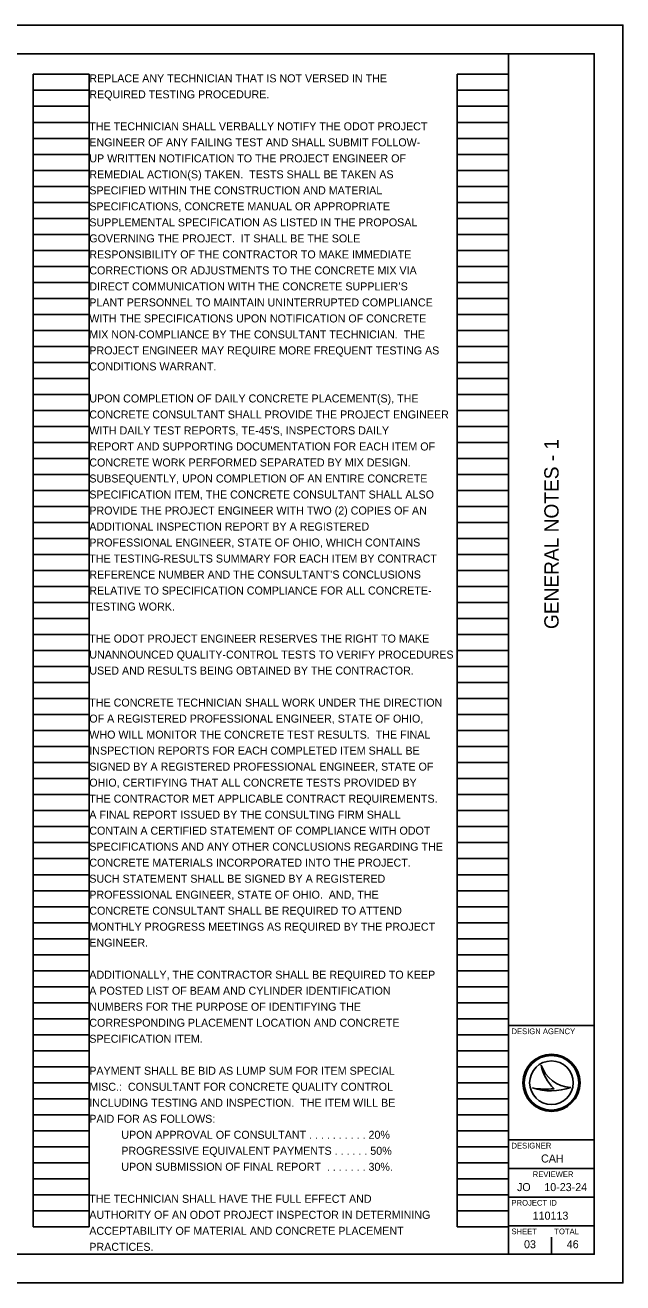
# Model space of a CAD drawing. Extents: x -15.3 to 74.8, y -11.5 to 47.6.
# Drawn here: x 23.54 to 34, y 0 to 22 of the extents above; entities that cross this region are included whole.
import ezdxf

# ---------------------------------------------------------------- set-up
doc = ezdxf.new("R2010")
doc.units = 0
for name, color, linetype in [('Default', 7, 'Continuous'), ('SH_Border', 7, 'Continuous'), ('SH_Cut_Line', 7, 'Continuous'), ('SH_Data', 7, 'Continuous')]:
    doc.layers.add(name, color=color, linetype=linetype)

msp = doc.modelspace()

# ---------------------------------------------------------------- linework, layer by layer
at = {"layer": 'SH_Border'}
for p, q in [((32, 0.5), (32, 21.5)), ((32, 4.5), (33.5, 4.5)), ((32, 2.5), (33.5, 2.5)), ((32, 2), (33.5, 2)), ((32, 1.5), (33.5, 1.5)), ((32, 1), (33.5, 1))]:
    msp.add_line(p, q, dxfattribs=at)
msp.add_lwpolyline([(1.5, 21.5), (33.5, 21.5), (33.5, 0.5), (1.5, 0.5)], close=True, dxfattribs=at)
at = {"layer": 'SH_Cut_Line'}
msp.add_lwpolyline([(0, 0), (34, 0), (34, 22), (0, 22)], close=True, dxfattribs=at)
at = {"layer": 'SH_Data'}
for p, q in [((23.68, 0.98), (23.68, 21.14)), ((23.68, 21.14), (24.66, 21.14)), ((24.66, 0.98), (24.66, 21.14)), ((31.1, 0.98), (31.1, 21.14)), ((31.1, 21.14), (32, 21.14)), ((32, 0.98), (32, 21.14)), ((23.68, 20.86), (24.66, 20.86)), ((31.1, 20.86), (32, 20.86)), ((23.68, 20.58), (24.66, 20.58)), ((31.1, 20.58), (32, 20.58)), ((23.68, 20.3), (24.66, 20.3)), ((31.1, 20.3), (32, 20.3)), ((23.68, 20.02), (24.66, 20.02)), ((31.1, 20.02), (32, 20.02)), ((23.68, 19.74), (24.66, 19.74)), ((31.1, 19.74), (32, 19.74)), ((23.68, 19.46), (24.66, 19.46)), ((31.1, 19.46), (32, 19.46)), ((23.68, 19.18), (24.66, 19.18)), ((31.1, 19.18), (32, 19.18)), ((23.68, 18.9), (24.66, 18.9)), ((31.1, 18.9), (32, 18.9)), ((23.68, 18.62), (24.66, 18.62)), ((31.1, 18.62), (32, 18.62)), ((23.68, 18.34), (24.66, 18.34)), ((31.1, 18.34), (32, 18.34)), ((23.68, 18.06), (24.66, 18.06)), ((31.1, 18.06), (32, 18.06)), ((23.68, 17.78), (24.66, 17.78)), ((31.1, 17.78), (32, 17.78)), ((23.68, 17.5), (24.66, 17.5)), ((31.1, 17.5), (32, 17.5)), ((23.68, 17.22), (24.66, 17.22)), ((31.1, 17.22), (32, 17.22)), ((23.68, 16.94), (24.66, 16.94)), ((31.1, 16.94), (32, 16.94)), ((23.68, 16.66), (24.66, 16.66)), ((31.1, 16.66), (32, 16.66)), ((23.68, 16.38), (24.66, 16.38)), ((31.1, 16.38), (32, 16.38)), ((23.68, 16.1), (24.66, 16.1)), ((31.1, 16.1), (32, 16.1)), ((23.68, 15.82), (24.66, 15.82)), ((31.1, 15.82), (32, 15.82)), ((23.68, 15.54), (24.66, 15.54)), ((31.1, 15.54), (32, 15.54)), ((23.68, 15.26), (24.66, 15.26)), ((31.1, 15.26), (32, 15.26)), ((23.68, 14.98), (24.66, 14.98)), ((31.1, 14.98), (32, 14.98)), ((23.68, 14.7), (24.66, 14.7)), ((31.1, 14.7), (32, 14.7)), ((23.68, 14.42), (24.66, 14.42)), ((31.1, 14.42), (32, 14.42)), ((23.68, 14.14), (24.66, 14.14)), ((31.1, 14.14), (32, 14.14)), ((23.68, 13.86), (24.66, 13.86)), ((31.1, 13.86), (32, 13.86)), ((23.68, 13.58), (24.66, 13.58)), ((31.1, 13.58), (32, 13.58)), ((23.68, 13.3), (24.66, 13.3)), ((31.1, 13.3), (32, 13.3)), ((23.68, 13.02), (24.66, 13.02)), ((31.1, 13.02), (32, 13.02)), ((23.68, 12.74), (24.66, 12.74)), ((31.1, 12.74), (32, 12.74)), ((23.68, 12.46), (24.66, 12.46)), ((31.1, 12.46), (32, 12.46)), ((23.68, 12.18), (24.66, 12.18)), ((31.1, 12.18), (32, 12.18)), ((23.68, 11.9), (24.66, 11.9)), ((31.1, 11.9), (32, 11.9)), ((23.68, 11.62), (24.66, 11.62)), ((31.1, 11.62), (32, 11.62)), ((23.68, 11.34), (24.66, 11.34)), ((31.1, 11.34), (32, 11.34)), ((23.68, 11.06), (24.66, 11.06)), ((31.1, 11.06), (32, 11.06)), ((23.68, 10.78), (24.66, 10.78)), ((31.1, 10.78), (32, 10.78)), ((23.68, 10.5), (24.66, 10.5)), ((31.1, 10.5), (32, 10.5)), ((23.68, 10.22), (24.66, 10.22)), ((31.1, 10.22), (32, 10.22)), ((23.68, 9.94), (24.66, 9.94)), ((31.1, 9.94), (32, 9.94)), ((23.68, 9.66), (24.66, 9.66)), ((31.1, 9.66), (32, 9.66)), ((23.68, 9.38), (24.66, 9.38)), ((31.1, 9.38), (32, 9.38)), ((23.68, 9.1), (24.66, 9.1)), ((31.1, 9.1), (32, 9.1)), ((23.68, 8.82), (24.66, 8.82)), ((31.1, 8.82), (32, 8.82)), ((23.68, 8.54), (24.66, 8.54)), ((31.1, 8.54), (32, 8.54)), ((23.68, 8.26), (24.66, 8.26)), ((31.1, 8.26), (32, 8.26)), ((23.68, 7.98), (24.66, 7.98)), ((31.1, 7.98), (32, 7.98)), ((23.68, 7.7), (24.66, 7.7)), ((31.1, 7.7), (32, 7.7)), ((23.68, 7.42), (24.66, 7.42)), ((31.1, 7.42), (32, 7.42)), ((23.68, 7.14), (24.66, 7.14)), ((31.1, 7.14), (32, 7.14)), ((23.68, 6.86), (24.66, 6.86)), ((31.1, 6.86), (32, 6.86)), ((23.68, 6.58), (24.66, 6.58)), ((31.1, 6.58), (32, 6.58)), ((23.68, 6.3), (24.66, 6.3)), ((31.1, 6.3), (32, 6.3)), ((23.68, 6.02), (24.66, 6.02)), ((31.1, 6.02), (32, 6.02)), ((23.68, 5.74), (24.66, 5.74)), ((31.1, 5.74), (32, 5.74)), ((23.68, 5.46), (24.66, 5.46)), ((31.1, 5.46), (32, 5.46)), ((23.68, 5.18), (24.66, 5.18)), ((31.1, 5.18), (32, 5.18)), ((23.68, 4.9), (24.66, 4.9)), ((31.1, 4.9), (32, 4.9)), ((23.68, 4.62), (24.66, 4.62)), ((31.1, 4.62), (32, 4.62)), ((23.68, 4.34), (24.66, 4.34)), ((31.1, 4.34), (32, 4.34)), ((23.68, 4.06), (24.66, 4.06)), ((31.1, 4.06), (32, 4.06)), ((23.68, 3.78), (24.66, 3.78)), ((31.1, 3.78), (32, 3.78)), ((32.567, 3.81), (32.567, 3.81)), ((23.68, 3.5), (24.66, 3.5)), ((31.1, 3.5), (32, 3.5)), ((32.417, 3.41), (32.417, 3.41)), ((32.75, 3.5), (32.75, 3.5)), ((33.087, 3.419), (33.087, 3.419)), ((23.68, 3.22), (24.66, 3.22)), ((31.1, 3.22), (32, 3.22)), ((23.68, 2.94), (24.66, 2.94)), ((31.1, 2.94), (32, 2.94)), ((23.68, 2.66), (24.66, 2.66)), ((31.1, 2.66), (32, 2.66)), ((23.68, 2.38), (24.66, 2.38)), ((31.1, 2.38), (32, 2.38)), ((23.68, 2.1), (24.66, 2.1)), ((31.1, 2.1), (32, 2.1)), ((23.68, 1.82), (24.66, 1.82)), ((31.1, 1.82), (32, 1.82)), ((23.68, 1.54), (24.66, 1.54)), ((31.1, 1.54), (32, 1.54)), ((23.68, 1.26), (24.66, 1.26)), ((31.1, 1.26), (32, 1.26)), ((23.68, 0.98), (24.66, 0.98)), ((31.1, 0.98), (32, 0.98)), ((32.375, 0.675), (32.375, 0.675)), ((32.75, 0.5), (32.75, 0.8))]:
    msp.add_line(p, q, dxfattribs=at)
for radius in [0.5, 0.477, 0.477, 0.382]:
    msp.add_circle((32.75, 3.5), radius, dxfattribs=at)
for centre, radius, start, end in [((33.116, 3.998), 0.58, 198.9257, 198.9319), ((33.347, 3.97), 0.796, 191.6379, 191.6421), ((33.116, 3.998), 0.58, 198.9319, 267.1657), ((33.347, 3.97), 0.796, 191.6421, 226.0947), ((32.739, 4.37), 1.013, 251.4576, 290.0832), ((32.648, 4.654), 1.266, 259.4964, 259.4995), ((32.739, 4.37), 1.013, 251.4527, 251.4576), ((32.648, 4.654), 1.266, 259.4995, 276.6672)]:
    msp.add_arc(centre, radius, start, end, dxfattribs=at)

# ---------------------------------------------------------------- texts
at = {"layer": 'Default'}
for s, p in [('REPLACE ANY TECHNICIAN THAT IS NOT VERSED IN THE ', (24.66, 21)), ('REQUIRED TESTING PROCEDURE.', (24.66, 20.72)), ('THE TECHNICIAN SHALL VERBALLY NOTIFY THE ODOT PROJECT ', (24.66, 20.16)), ('ENGINEER OF ANY FAILING TEST AND SHALL SUBMIT FOLLOW-', (24.66, 19.88)), ('UP WRITTEN NOTIFICATION TO THE PROJECT ENGINEER OF ', (24.66, 19.6)), ('REMEDIAL ACTION(S) TAKEN.  TESTS SHALL BE TAKEN AS ', (24.66, 19.32)), ('SPECIFIED WITHIN THE CONSTRUCTION AND MATERIAL ', (24.66, 19.04)), ('SPECIFICATIONS, CONCRETE MANUAL OR APPROPRIATE ', (24.66, 18.76)), ('SUPPLEMENTAL SPECIFICATION AS LISTED IN THE PROPOSAL ', (24.66, 18.48)), ('GOVERNING THE PROJECT.  IT SHALL BE THE SOLE ', (24.66, 18.2)), ('RESPONSIBILITY OF THE CONTRACTOR TO MAKE IMMEDIATE ', (24.66, 17.92)), ('CORRECTIONS OR ADJUSTMENTS TO THE CONCRETE MIX VIA ', (24.66, 17.64)), ('DIRECT COMMUNICATION WITH THE CONCRETE SUPPLIER’S ', (24.66, 17.36)), ('PLANT PERSONNEL TO MAINTAIN UNINTERRUPTED COMPLIANCE ', (24.66, 17.08)), ('WITH THE SPECIFICATIONS UPON NOTIFICATION OF CONCRETE ', (24.66, 16.8)), ('MIX NON-COMPLIANCE BY THE CONSULTANT TECHNICIAN.  THE ', (24.66, 16.52)), ('PROJECT ENGINEER MAY REQUIRE MORE FREQUENT TESTING AS ', (24.66, 16.24)), ('CONDITIONS WARRANT.', (24.66, 15.96)), ('UPON COMPLETION OF DAILY CONCRETE PLACEMENT(S), THE ', (24.66, 15.4)), ('CONCRETE CONSULTANT SHALL PROVIDE THE PROJECT ENGINEER ', (24.66, 15.12)), ("WITH DAILY TEST REPORTS, TE-45'S, INSPECTORS DAILY ", (24.66, 14.84)), ('REPORT AND SUPPORTING DOCUMENTATION FOR EACH ITEM OF ', (24.66, 14.56)), ('CONCRETE WORK PERFORMED SEPARATED BY MIX DESIGN.  ', (24.66, 14.28)), ('SUBSEQUENTLY, UPON COMPLETION OF AN ENTIRE CONCRETE ', (24.66, 14)), ('SPECIFICATION ITEM, THE CONCRETE CONSULTANT SHALL ALSO ', (24.66, 13.72)), ('PROVIDE THE PROJECT ENGINEER WITH TWO (2) COPIES OF AN ', (24.66, 13.44)), ('ADDITIONAL INSPECTION REPORT BY A REGISTERED ', (24.66, 13.16)), ('PROFESSIONAL ENGINEER, STATE OF OHIO, WHICH CONTAINS ', (24.66, 12.88)), ('THE TESTING-RESULTS SUMMARY FOR EACH ITEM BY CONTRACT ', (24.66, 12.6)), ('REFERENCE NUMBER AND THE CONSULTANT’S CONCLUSIONS ', (24.66, 12.32)), ('RELATIVE TO SPECIFICATION COMPLIANCE FOR ALL CONCRETE-', (24.66, 12.04)), ('TESTING WORK.', (24.66, 11.76)), ('THE ODOT PROJECT ENGINEER RESERVES THE RIGHT TO MAKE ', (24.66, 11.2)), ('UNANNOUNCED QUALITY-CONTROL TESTS TO VERIFY PROCEDURES ', (24.66, 10.92)), ('USED AND RESULTS BEING OBTAINED BY THE CONTRACTOR.', (24.66, 10.64)), ('THE CONCRETE TECHNICIAN SHALL WORK UNDER THE DIRECTION ', (24.66, 10.08)), ('OF A REGISTERED PROFESSIONAL ENGINEER, STATE OF OHIO, ', (24.66, 9.8)), ('WHO WILL MONITOR THE CONCRETE TEST RESULTS.  THE FINAL ', (24.66, 9.52)), ('INSPECTION REPORTS FOR EACH COMPLETED ITEM SHALL BE ', (24.66, 9.24)), ('SIGNED BY A REGISTERED PROFESSIONAL ENGINEER, STATE OF ', (24.66, 8.96)), ('OHIO, CERTIFYING THAT ALL CONCRETE TESTS PROVIDED BY ', (24.66, 8.68)), ('THE CONTRACTOR MET APPLICABLE CONTRACT REQUIREMENTS.  ', (24.66, 8.4)), ('A FINAL REPORT ISSUED BY THE CONSULTING FIRM SHALL ', (24.66, 8.12)), ('CONTAIN A CERTIFIED STATEMENT OF COMPLIANCE WITH ODOT ', (24.66, 7.84)), ('SPECIFICATIONS AND ANY OTHER CONCLUSIONS REGARDING THE ', (24.66, 7.56)), ('CONCRETE MATERIALS INCORPORATED INTO THE PROJECT.  ', (24.66, 7.28)), ('SUCH STATEMENT SHALL BE SIGNED BY A REGISTERED ', (24.66, 7)), ('PROFESSIONAL ENGINEER, STATE OF OHIO.  AND, THE ', (24.66, 6.72)), ('CONCRETE CONSULTANT SHALL BE REQUIRED TO ATTEND ', (24.66, 6.44)), ('MONTHLY PROGRESS MEETINGS AS REQUIRED BY THE PROJECT ', (24.66, 6.16)), ('ENGINEER.', (24.66, 5.88)), ('ADDITIONALLY, THE CONTRACTOR SHALL BE REQUIRED TO KEEP ', (24.66, 5.32)), ('A POSTED LIST OF BEAM AND CYLINDER IDENTIFICATION ', (24.66, 5.04)), ('NUMBERS FOR THE PURPOSE OF IDENTIFYING THE ', (24.66, 4.76)), ('CORRESPONDING PLACEMENT LOCATION AND CONCRETE ', (24.66, 4.48)), ('SPECIFICATION ITEM.', (24.66, 4.2)), ('PAYMENT SHALL BE BID AS LUMP SUM FOR ITEM SPECIAL ', (24.66, 3.64)), ('MISC.:  CONSULTANT FOR CONCRETE QUALITY CONTROL ', (24.66, 3.36)), ('INCLUDING TESTING AND INSPECTION.  THE ITEM WILL BE ', (24.66, 3.08)), ('PAID FOR AS FOLLOWS:', (24.66, 2.8)), ('UPON APPROVAL OF CONSULTANT . . . . . . . . . . 20%', (25.22, 2.52)), ('PROGRESSIVE EQUIVALENT PAYMENTS . . . . . . 50%', (25.22, 2.24)), ('UPON SUBMISSION OF FINAL REPORT  . . . . . . . 30%.', (25.22, 1.96)), ('THE TECHNICIAN SHALL HAVE THE FULL EFFECT AND ', (24.66, 1.4)), ('AUTHORITY OF AN ODOT PROJECT INSPECTOR IN DETERMINING ', (24.66, 1.12)), ('ACCEPTABILITY OF MATERIAL AND CONCRETE PLACEMENT ', (24.66, 0.84)), ('PRACTICES.', (24.66, 0.56))]:
    msp.add_text(s, height=0.14, dxfattribs=at).set_placement(p)
at = {"layer": 'SH_Data'}
msp.add_text('GENERAL NOTES - 1', height=0.25, rotation=90, dxfattribs=at).set_placement((32.875, 11.437))
for s, height, p in [('DESIGN AGENCY', 0.1, (32.05, 4.35)), ('DESIGNER', 0.1, (32.05, 2.35)), ('CAH', 0.14, (32.568, 2.105)), ('REVIEWER', 0.1, (32.422, 1.85)), ('JO', 0.14, (32.147, 1.605)), ('10-23-24', 0.14, (32.625, 1.605)), ('PROJECT ID', 0.1, (32.05, 1.35)), ('110113', 0.14, (32.421, 1.105)), ('SHEET', 0.1, (32.05, 0.85)), ('TOTAL', 0.1, (32.8, 0.85)), ('03', 0.14, (32.27, 0.605)), ('46', 0.14, (33.018, 0.605))]:
    msp.add_text(s, height=height, dxfattribs=at).set_placement(p)

doc.saveas('drawing.dxf')
